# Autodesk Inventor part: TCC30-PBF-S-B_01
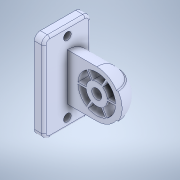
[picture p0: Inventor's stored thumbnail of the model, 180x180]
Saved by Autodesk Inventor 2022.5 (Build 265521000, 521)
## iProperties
Created: 2023-09
Part Number: TCC30-PBF-S-B_01
Material: 一般
Document SubType Name: Modeling
Designer: ImaoCorp
Density: 1 g/cm^3
Appearance: 既定
Author: ImaoCorp
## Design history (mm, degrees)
feature "TCC30-PBF-S-B_01"
node "ソリッド1"
